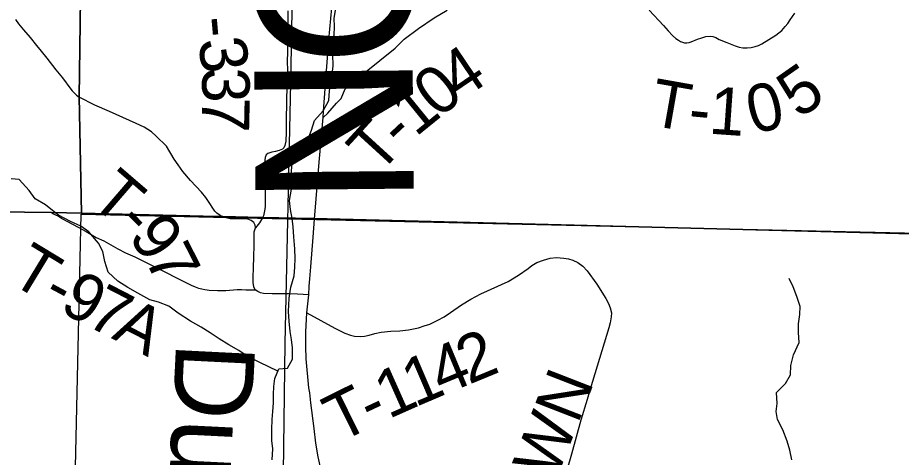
# Model space of a CAD drawing. Extents: x 0 to 34, y 0 to 22.
# Drawn here: x 5.272 to 6.329, y 15.28 to 15.806 of the extents above; entities that cross this region are included whole.
import ezdxf

# ---------------------------------------------------------------- set-up
doc = ezdxf.new("R2010")
doc.units = 0
for name, color, linetype in [('GM_X_Corporation', 7, 'Continuous'), ('GM_X_County_Text', 7, 'Continuous'), ('GM_X_Minor_River', 7, 'Continuous'), ('GM_X_Minor_River_Text', 7, 'Continuous'), ('GM_X_Rail_Line', 7, 'Continuous'), ('GM_X_State_Route', 7, 'Continuous'), ('GM_X_Township_Road', 7, 'Continuous'), ('GM_X_Township_Road_Text', 7, 'Continuous')]:
    doc.layers.add(name, color=color, linetype=linetype)

msp = doc.modelspace()

# ---------------------------------------------------------------- linework, layer by layer
at = {"layer": 'GM_X_Corporation'}
for points in [[(2.9828, 15.6366), (4.3545, 15.5959), (4.7469, 15.5851), (4.7491, 15.5839), (4.752, 15.583), (4.7567, 15.5825), (4.8249, 15.5815), (4.8348, 15.5815), (4.8639, 15.5808), (4.8707, 15.5807), (4.875, 15.5807), (4.8836, 15.5806), (4.9014, 15.5802), (4.9151, 15.5796), (4.9231, 15.5793), (4.936, 15.5788), (4.9453, 15.5784), (4.9558, 15.5778), (5.3123, 15.5731), (5.3483, 15.5723), (5.3453, 15.7118), (5.3543, 16.3597), (5.3699, 17.5116)], [(5.3699, 17.5116), (5.3543, 16.3597), (5.3453, 15.7118), (5.3483, 15.5723), (5.3123, 15.5731), (4.9558, 15.5778), (4.9453, 15.5784), (4.936, 15.5788), (4.9231, 15.5793), (4.9151, 15.5796), (4.9014, 15.5802), (4.8836, 15.5806), (4.875, 15.5807), (4.8707, 15.5807), (4.8639, 15.5808), (4.8348, 15.5815), (4.8249, 15.5815), (4.7567, 15.5825), (4.752, 15.583), (4.7491, 15.5839), (4.7469, 15.5851), (4.3545, 15.5959), (2.9828, 15.6366)], [(2.9828, 15.6366), (4.3545, 15.5959), (4.7469, 15.5851), (4.7491, 15.5839), (4.752, 15.583), (4.7567, 15.5825), (4.8249, 15.5815), (4.8348, 15.5815), (4.8639, 15.5808), (4.8707, 15.5807), (4.875, 15.5807), (4.8836, 15.5806), (4.9014, 15.5802), (4.9151, 15.5796), (4.9231, 15.5793), (4.936, 15.5788), (4.9453, 15.5784), (4.9558, 15.5778), (5.3123, 15.5731), (5.3483, 15.5723), (5.3453, 15.7118), (5.3543, 16.3597), (5.3699, 17.5116)], [(5.3699, 17.5116), (5.3543, 16.3597), (5.3453, 15.7118), (5.3483, 15.5723), (5.5099, 15.5686), (5.5173, 15.5684), (5.5624, 15.5674), (5.5643, 15.5673), (5.624, 15.566), (5.6266, 15.5659), (7.0561, 15.5293), (7.0614, 15.5292), (7.2766, 15.5247), (7.2802, 15.5246), (7.2927, 15.5244), (7.5593, 15.5188), (7.5629, 15.5187), (8.3936, 15.4979)], [(7.0561, 15.5293), (5.6266, 15.5659), (5.624, 15.566), (5.5643, 15.5673), (5.5624, 15.5674), (5.5173, 15.5684), (5.5099, 15.5686), (5.3483, 15.5723), (5.3123, 15.5731), (4.9558, 15.5778)]]:
    msp.add_lwpolyline(points, dxfattribs=at)
msp.add_lwpolyline([(5.3476, 15.5712), (6.3676, 15.5481), (6.4093, 15.5478), (6.383, 14.5028), (5.3249, 14.5126), (5.3254, 14.5744)], close=True, dxfattribs=at)
at = {"layer": 'GM_X_Minor_River'}
for points in [[(5.5762, 15.2771), (5.5769, 15.2904), (5.5757, 15.3003), (5.5757, 15.3135), (5.576, 15.3253), (5.5768, 15.3351), (5.5779, 15.3454), (5.5778, 15.3552), (5.5782, 15.3651), (5.5793, 15.3746), (5.5842, 15.3863), (5.5944, 15.3871), (5.6004, 15.3978), (5.6004, 15.4114), (5.5992, 15.4213), (5.5977, 15.4308), (5.5965, 15.4433), (5.5957, 15.4546), (5.5964, 15.4706), (5.5986, 15.4838), (5.6024, 15.4975), (5.6031, 15.5077), (5.6035, 15.518), (5.6031, 15.5297), (5.6019, 15.5441), (5.6011, 15.5562), (5.5999, 15.5661), (5.598, 15.5767), (5.5968, 15.5877), (5.5991, 15.601), (5.5994, 15.6105), (5.5994, 15.623), (5.6005, 15.6359), (5.6114, 15.6465), (5.6189, 15.6602), (5.6231, 15.6716), (5.6268, 15.6833), (5.637, 15.6951), (5.6438, 15.7073), (5.6449, 15.7187), (5.6471, 15.7338), (5.649, 15.7482), (5.6489, 15.7626), (5.6466, 15.7736), (5.6504, 15.7854), (5.6507, 15.796), (5.6503, 15.8055), (5.6518, 15.8153)], [(5.3205, 15.57), (5.3175, 15.5724), (5.3052, 15.5823), (5.2928, 15.5896), (5.2856, 15.5994), (5.2737, 15.6126), (5.2639, 15.6136)], [(5.5829, 15.3833), (5.5614, 15.3935), (5.5466, 15.401), (5.5364, 15.4082), (5.5243, 15.415), (5.5129, 15.4221), (5.5019, 15.4293), (5.4913, 15.4361), (5.4784, 15.4432), (5.4639, 15.4527), (5.4526, 15.4613), (5.4404, 15.4658), (5.4298, 15.4688), (5.4154, 15.4768), (5.4037, 15.4835), (5.3915, 15.4911), (5.3801, 15.5017), (5.3759, 15.5145), (5.3736, 15.5267), (5.3683, 15.5365), (5.3569, 15.5501), (5.3474, 15.5569), (5.3349, 15.5625), (5.3205, 15.57)], [(6.1979, 15.2774), (6.1952, 15.2888), (6.1921, 15.2994), (6.1868, 15.313), (6.1807, 15.3255), (6.1791, 15.335), (6.1803, 15.3448), (6.1795, 15.3577), (6.19, 15.3687), (6.1961, 15.379), (6.1964, 15.39), (6.1998, 15.4029), (6.2065, 15.4177), (6.2057, 15.4295), (6.2057, 15.4401), (6.2072, 15.4511), (6.2075, 15.4606), (6.2037, 15.4727), (6.1991, 15.4844), (6.1946, 15.4942)]]:
    msp.add_lwpolyline(points, dxfattribs=at)
at = {"layer": 'GM_X_Rail_Line'}
msp.add_lwpolyline([(5.5863, 14.9831), (5.5917, 15.417), (5.5983, 15.728), (5.6042, 16.0294), (5.6055, 16.1024), (5.6057, 16.1543), (5.6178, 16.2094), (5.6443, 16.2738), (5.6648, 16.3404), (5.6894, 16.4026), (5.7035, 16.455), (5.7074, 16.5065), (5.7067, 16.5743), (5.691, 16.6283)], dxfattribs=at)
at = {"layer": 'GM_X_State_Route'}
for points in [[(5.6213, 15.4938), (5.6226, 15.5084), (5.6251, 15.5438), (5.6268, 15.5654), (5.6324, 15.6335), (5.6371, 15.6868), (5.6376, 15.6947), (5.6441, 15.7798), (5.6489, 15.8313)], [(5.62, 15.4746), (5.6206, 15.485), (5.6213, 15.4938)], [(5.636, 15.2592), (5.6311, 15.2807), (5.6285, 15.2972), (5.6263, 15.3148), (5.6225, 15.3456), (5.6211, 15.3572), (5.6201, 15.3632), (5.617, 15.3981), (5.6166, 15.413), (5.6165, 15.4305), (5.6178, 15.4532), (5.62, 15.4746)]]:
    msp.add_lwpolyline(points, dxfattribs=at)
at = {"layer": 'GM_X_Township_Road'}
for points in [[(5.595, 15.8146), (5.5948, 15.8061), (5.5945, 15.7778), (5.5945, 15.7665), (5.5943, 15.753), (5.5946, 15.7445), (5.5944, 15.7358), (5.5939, 15.7252), (5.5934, 15.7056), (5.5931, 15.6839), (5.593, 15.6692), (5.5924, 15.6586), (5.5913, 15.6536), (5.59, 15.6506), (5.5885, 15.6492), (5.5847, 15.6476), (5.5803, 15.6464), (5.5758, 15.6454), (5.5708, 15.6439), (5.5688, 15.6421), (5.5678, 15.639), (5.5673, 15.6361), (5.568, 15.6241), (5.5679, 15.5983), (5.5679, 15.5878), (5.5678, 15.5807), (5.5675, 15.5772), (5.5668, 15.5733), (5.5657, 15.5693), (5.5645, 15.5668), (5.5609, 15.5609), (5.5562, 15.555)], [(5.6371, 15.6868), (5.6428, 15.6923), (5.653, 15.7039), (5.6585, 15.7098), (5.6633, 15.7212), (5.6731, 15.7292), (5.6866, 15.7403), (5.7231, 15.7698), (5.734, 15.7807), (5.7511, 15.7933), (5.7698, 15.8064), (5.7856, 15.8156)], [(6.0269, 15.8154), (6.0443, 15.7969), (6.0498, 15.7907), (6.0548, 15.7852), (6.059, 15.7814), (6.062, 15.7793), (6.0647, 15.778), (6.0693, 15.7764), (6.0723, 15.7762), (6.0751, 15.7768), (6.0772, 15.7775), (6.085, 15.7805), (6.09, 15.7823), (6.0949, 15.7837), (6.1, 15.7843), (6.1034, 15.7839), (6.1069, 15.7825), (6.1108, 15.7804), (6.1198, 15.7766), (6.13, 15.7728), (6.1346, 15.7712), (6.1391, 15.7704), (6.1441, 15.7704), (6.1491, 15.7707), (6.1539, 15.7718), (6.158, 15.7732), (6.1618, 15.7753), (6.1785, 15.7855), (6.1823, 15.7883), (6.1856, 15.7912), (6.1899, 15.7959), (6.1928, 15.7995), (6.1957, 15.8038), (6.2014, 15.812)], [(5.2691, 15.8041), (5.2728, 15.7992), (5.2786, 15.792), (5.2866, 15.7825), (5.2944, 15.773), (5.2999, 15.7662), (5.3066, 15.758), (5.3176, 15.7438), (5.3253, 15.7343), (5.3354, 15.721), (5.3371, 15.719), (5.3393, 15.7165), (5.3422, 15.7138), (5.3455, 15.7112)], [(5.5139, 15.5698), (5.5101, 15.5723), (5.5078, 15.5749), (5.4991, 15.5876), (5.4967, 15.5913), (5.4916, 15.5977), (5.4785, 15.6114), (5.4694, 15.6222), (5.4638, 15.6301), (5.459, 15.6372), (5.4498, 15.6526), (5.4375, 15.6647), (5.4317, 15.6699), (5.423, 15.6752), (5.4136, 15.6798), (5.3815, 15.6941), (5.364, 15.7018), (5.3455, 15.7112)], [(5.3125, 15.5726), (5.3206, 15.5688), (5.3254, 15.5657), (5.3305, 15.5629), (5.3443, 15.5558), (5.3536, 15.5506), (5.3656, 15.5435), (5.3747, 15.5392), (5.3914, 15.5298), (5.4006, 15.525), (5.4062, 15.5224), (5.4118, 15.52), (5.4272, 15.5124), (5.45, 15.501), (5.4603, 15.496), (5.4691, 15.4914), (5.4745, 15.4885), (5.4792, 15.4864), (5.4842, 15.4842), (5.4881, 15.4828), (5.492, 15.4817), (5.4957, 15.481), (5.4983, 15.4805), (5.501, 15.4802), (5.5106, 15.4798), (5.5209, 15.4798), (5.5344, 15.481), (5.5393, 15.4811), (5.5448, 15.4808), (5.5508, 15.4806), (5.556, 15.4808)], [(5.5562, 15.555), (5.5558, 15.5582), (5.5541, 15.5611), (5.5512, 15.5638), (5.547, 15.5652), (5.5429, 15.5655), (5.526, 15.5657), (5.5212, 15.5667), (5.5175, 15.5679), (5.5139, 15.5698)], [(5.62, 15.4746), (5.6065, 15.4754), (5.5968, 15.476), (5.5867, 15.476), (5.5761, 15.4758), (5.566, 15.4763), (5.5621, 15.4772), (5.559, 15.4786), (5.556, 15.4808), (5.5543, 15.4844), (5.5536, 15.4893), (5.5536, 15.497), (5.5539, 15.506), (5.5543, 15.5214), (5.5547, 15.5326), (5.5545, 15.5463), (5.5548, 15.5499), (5.5562, 15.555)], [(5.6178, 15.4532), (5.6512, 15.4346), (5.663, 15.4289), (5.6697, 15.4266), (5.6748, 15.4254), (5.682, 15.4249), (5.6868, 15.4253), (5.6922, 15.4266), (5.6991, 15.4286), (5.7067, 15.4299), (5.7182, 15.4314), (5.729, 15.4318), (5.7393, 15.4326), (5.751, 15.4351), (5.7581, 15.4374), (5.7647, 15.4397), (5.7742, 15.4442), (5.7819, 15.4485), (5.7896, 15.4537), (5.8028, 15.4629), (5.8136, 15.4694), (5.8257, 15.4758), (5.8584, 15.4907), (5.8709, 15.4983), (5.8824, 15.5062), (5.8868, 15.5096), (5.8927, 15.5132), (5.9006, 15.5162), (5.9087, 15.5186), (5.9164, 15.5192), (5.925, 15.5187), (5.9304, 15.5179), (5.9359, 15.5163), (5.9416, 15.5135), (5.9476, 15.5091), (5.953, 15.5035), (5.9643, 15.4873), (5.9754, 15.4704), (5.9785, 15.4643), (5.9806, 15.4591), (5.9819, 15.4531), (5.9818, 15.4485), (5.9804, 15.4412), (5.9788, 15.4353), (5.9678, 15.3985), (5.9566, 15.3617), (5.953, 15.3494), (5.9454, 15.3245), (5.9343, 15.2839), (5.9289, 15.2662)]]:
    msp.add_lwpolyline(points, dxfattribs=at)

# ---------------------------------------------------------------- texts
at = {"layer": 'GM_X_County_Text'}
for s, rotation, p in [('O', 89.5387, (5.7441, 15.7478)), ('N', 90.5179, (5.7457, 15.5811))]:
    msp.add_text(s, height=0.1894, rotation=rotation, dxfattribs=at).set_placement(p)
at = {"layer": 'GM_X_Minor_River_Text'}
msp.add_text('Duck', height=0.0947, rotation=267.1501, dxfattribs=at).set_placement((5.4614, 15.419))
at = {"layer": 'GM_X_Township_Road_Text'}
for s, height, rotation, p in [('-', 0.0568, 275.0908, (5.4847, 15.8061)), ('3', 0.0568, 278.5086, (5.4872, 15.7792)), ('4', 0.0568, 33.9888, (5.801, 15.7061)), ('0', 0.0568, 38.9321, (5.7748, 15.6849)), ('5', 0.0568, 35.045, (6.2063, 15.6845)), ('3', 0.0568, 270.6974, (5.4922, 15.7466)), ('T', 0.0568, 349.9719, (6.0259, 15.6781)), ('0', 0.0568, 13.4942, (6.1512, 15.6668)), ('1', 0.0568, 39.0759, (5.7477, 15.6629)), ('1', 0.0568, 355.9871, (6.0975, 15.6677)), ('7', 0.0568, 268.6989, (5.4927, 15.7121)), ('-', 0.0568, 354.5167, (6.0727, 15.67)), ('T', 0.0568, 47.607, (5.7036, 15.6171)), ('-', 0.0568, 43.1396, (5.7314, 15.6476)), ('T', 0.0568, 319.3043, (5.3564, 15.586)), ('-', 0.0568, 314.6909, (5.3878, 15.5591)), ('9', 0.0568, 307.2269, (5.4029, 15.544)), ('T', 0.0568, 328.7628, (5.2601, 15.4907)), ('7', 0.0568, 297.091, (5.4227, 15.5183)), ('9', 0.0568, 332.2211, (5.3202, 15.4558)), ('-', 0.0568, 331.7007, (5.2992, 15.4671)), ('7', 0.0568, 332.6839, (5.3516, 15.4392)), ('A', 0.0568, 332.8402, (5.3829, 15.4231)), ('2', 0.0568, 22.4633, (5.8114, 15.367)), ('4', 0.0568, 22.6103, (5.7791, 15.3536)), ('1', 0.0568, 23.1186, (5.747, 15.3399)), ('1', 0.0568, 23.9878, (5.7153, 15.3257)), ('BROWN', 0.05682, 68.739, (5.856, 15.0988)), ('T', 0.0568, 26.3312, (5.6566, 15.2972)), ('-', 0.0568, 25.1197, (5.6944, 15.3159))]:
    msp.add_text(s, height=height, rotation=rotation, dxfattribs=at).set_placement(p)

doc.saveas('drawing.dxf')
